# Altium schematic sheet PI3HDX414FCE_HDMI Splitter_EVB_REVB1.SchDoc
size 386 x 246 mm
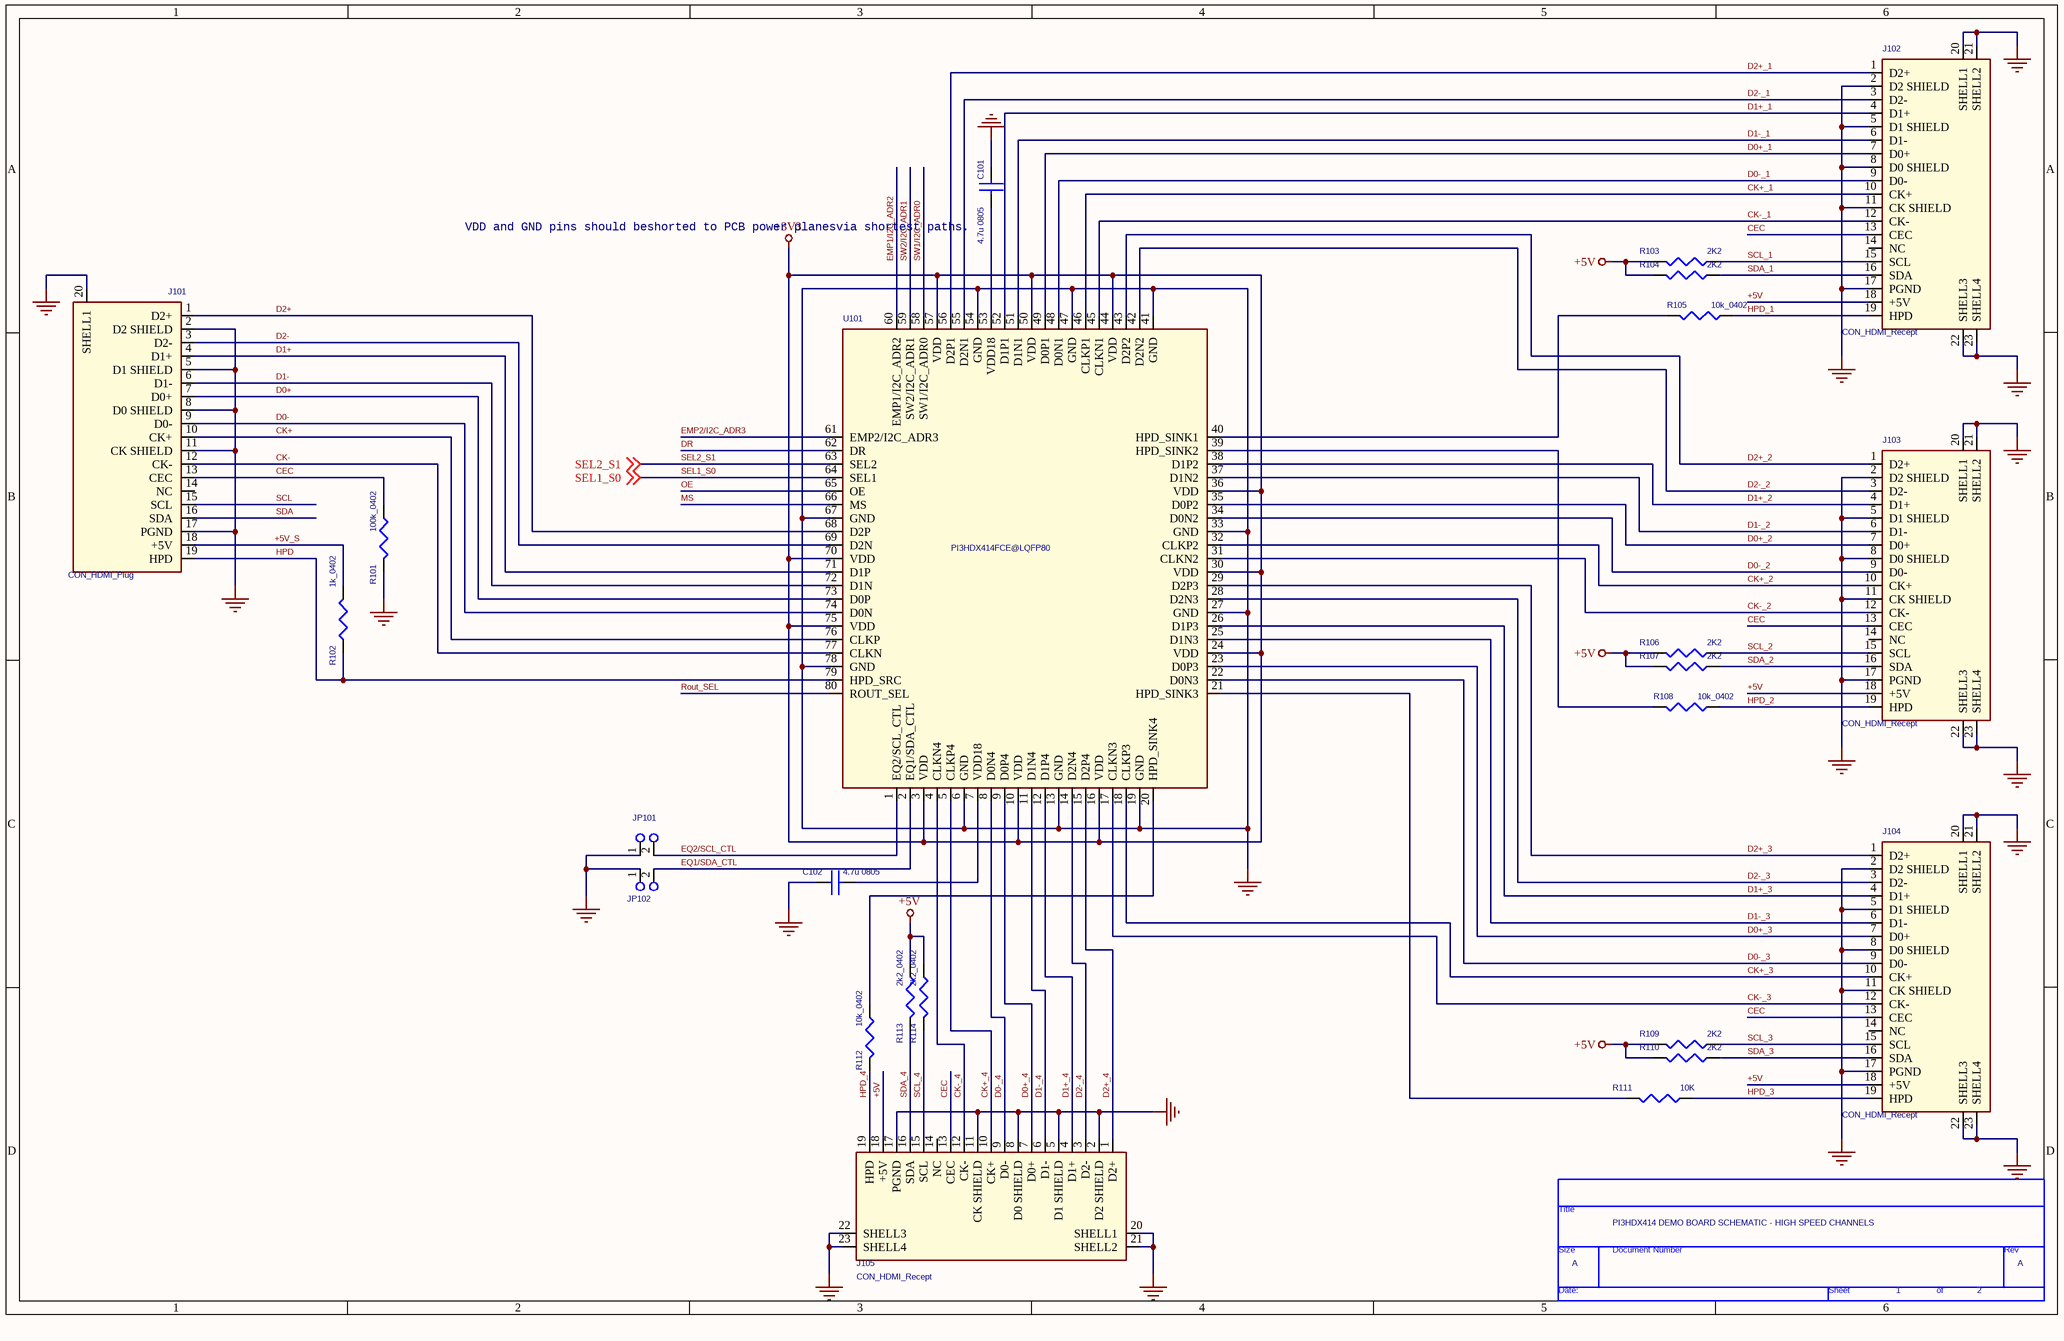
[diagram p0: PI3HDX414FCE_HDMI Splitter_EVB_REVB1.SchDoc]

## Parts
*  Page Count: 2  Page Number: 1  Page Size: A  Title: PI3HDX414 DEMO BOARD SCHEMATIC - HIGH SPEED CHANNELS  (hidden comment: TitleBlock0)  (graphical)
C101  4.7u 0805  [CAP@CC_0805]
C102  4.7u 0805  [CAP@CC_0805]
J101  CON_HDMI_Plug  [CON_HDMI_Plug]
J102  CON_HDMI_Recept  [CON_HDMI_Recept]
J103  CON_HDMI_Recept  [CON_HDMI_Recept]
J104  CON_HDMI_Recept  [CON_HDMI_Recept]
J105  CON_HDMI_Recept  [CON_HDMI_Recept]
JP101  2x1 Pin Header  [2x1 Pin Header]  (value not drawn)
JP102  2x1 Pin Header  [2x1 Pin Header]  (value not drawn)
R101  100k_0402  [R_0402]
R102  1k_0402  [R_0402]
R103  2K2  [RES@R_0402]
R104  2K2  [RES@R_0402]
R105  10k_0402  [R_0402]
R106  2K2  [RES@R_0402]
R107  2K2  [RES@R_0402]
R108  10k_0402  [R_0402]
R109  2K2  [RES@R_0402]
R110  2K2  [RES@R_0402]
R111  10K  [RES@R_0402]
R112  10k_0402  [R_0402]
R113  2k2_0402  [R_0402]
R114  2k2_0402  [R_0402]
U101  PI3HDX414FCE@LQFP80  [FC80]

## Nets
+3V3: U101.3(VDD) U101.10(VDD) U101.16(VDD) U101.24(VDD) U101.30(VDD) U101.36(VDD) U101.44(VDD) U101.50(VDD) U101.57(VDD) U101.70(VDD) U101.75(VDD)
+5V: J102.18(+5V) J103.18(+5V) J104.18(+5V) J105.18(+5V) R103.2 R104.2 R106.2 R107.2 R109.2 R110.2 R113.1 R114.1
GND: C101.1 C102.1 J101.2(D2_SHIELD) J101.5(D1_SHIELD) J101.8(D0_SHIELD) J101.11(CK_SHIELD) J101.17(PGND) J101.20(SHELL1) J102.2(D2_SHIELD) J102.5(D1_SHIELD) J102.8(D0_SHIELD) J102.11(CK_SHIELD) J102.17(PGND) J102.20(SHELL1) J102.21(SHELL2) J102.22(SHELL3) J102.23(SHELL4) J103.2(D2_SHIELD) J103.5(D1_SHIELD) J103.8(D0_SHIELD) J103.11(CK_SHIELD) J103.17(PGND) J103.20(SHELL1) J103.21(SHELL2) J103.22(SHELL3) J103.23(SHELL4) J104.2(D2_SHIELD) J104.5(D1_SHIELD) J104.8(D0_SHIELD) J104.11(CK_SHIELD) J104.17(PGND) J104.20(SHELL1) J104.21(SHELL2) J104.22(SHELL3) J104.23(SHELL4) J105.2(D2_SHIELD) J105.5(D1_SHIELD) J105.8(D0_SHIELD) J105.11(CK_SHIELD) J105.17(PGND) J105.20(SHELL1) J105.21(SHELL2) J105.22(SHELL3) J105.23(SHELL4) JP101.1 JP102.1 R101.2 U101.6(GND) U101.13(GND) U101.19(GND) U101.27(GND) U101.33(GND) U101.41(GND) U101.47(GND) U101.54(GND) U101.67(GND) U101.78(GND)
+5V_S: J101.18(+5V) R102.2
CEC: J101.13(CEC) J102.13(CEC) J103.13(CEC) J104.13(CEC) J105.13(CEC) R101.1
CK+: J101.10(CK+) U101.76(CLKP)
CK+_1: J102.10(CK+) U101.46(CLKP1)
CK+_2: J103.10(CK+) U101.32(CLKP2)
CK+_3: J104.10(CK+) U101.18(CLKP3)
CK+_4: J105.10(CK+) U101.5(CLKP4)
CK-: J101.12(CK-) U101.77(CLKN)
CK-_1: J102.12(CK-) U101.45(CLKN1)
CK-_2: J103.12(CK-) U101.31(CLKN2)
CK-_3: J104.12(CK-) U101.17(CLKN3)
CK-_4: J105.12(CK-) U101.4(CLKN4)
D0+: J101.7(D0+) U101.73(D0P)
D0+_1: J102.7(D0+) U101.49(D0P1)
D0+_2: J103.7(D0+) U101.35(D0P2)
D0+_3: J104.7(D0+) U101.23(D0P3)
D0+_4: J105.7(D0+) U101.9(D0P4)
D0-: J101.9(D0-) U101.74(D0N)
D0-_1: J102.9(D0-) U101.48(D0N1)
D0-_2: J103.9(D0-) U101.34(D0N2)
D0-_3: J104.9(D0-) U101.22(D0N3)
D0-_4: J105.9(D0-) U101.8(D0N4)
D1+: J101.4(D1+) U101.71(D1P)
D1+_1: J102.4(D1+) U101.52(D1P1)
D1+_2: J103.4(D1+) U101.38(D1P2)
D1+_3: J104.4(D1+) U101.26(D1P3)
D1+_4: J105.4(D1+) U101.12(D1P4)
D1-: J101.6(D1-) U101.72(D1N)
D1-_1: J102.6(D1-) U101.51(D1N1)
D1-_2: J103.6(D1-) U101.37(D1N2)
D1-_3: J104.6(D1-) U101.25(D1N3)
D1-_4: J105.6(D1-) U101.11(D1N4)
D2+: J101.1(D2+) U101.68(D2P)
D2+_1: J102.1(D2+) U101.56(D2P1)
D2+_2: J103.1(D2+) U101.43(D2P2)
D2+_3: J104.1(D2+) U101.29(D2P3)
D2+_4: J105.1(D2+) U101.15(D2P4)
D2-: J101.3(D2-) U101.69(D2N)
D2-_1: J102.3(D2-) U101.55(D2N1)
D2-_2: J103.3(D2-) U101.42(D2N2)
D2-_3: J104.3(D2-) U101.28(D2N3)
D2-_4: J105.3(D2-) U101.14(D2N4)
DR: U101.62(DR)
EMP1/I2C_ADR2: U101.60(EMP1/I2C_ADR2)
EMP2/I2C_ADR3: U101.61(EMP2/I2C_ADR3)
EQ1/SDA_CTL: JP102.2 U101.2(EQ1/SDA_CTL)
EQ2/SCL_CTL: JP101.2 U101.1(EQ2/SCL_CTL)
HPD: J101.19(HPD) R102.1 U101.79(HPD_SRC)
HPD_1: J102.19(HPD) R105.1
HPD_2: J103.19(HPD) R108.1
HPD_3: J104.19(HPD) R111.1
HPD_4: J105.19(HPD) R112.2
MS: U101.66(MS)
OE: U101.65(OE)
Rout_SEL: U101.80(ROUT_SEL)
SCL: J101.15(SCL)
SCL_1: J102.15(SCL) R103.1
SCL_2: J103.15(SCL) R106.1
SCL_3: J104.15(SCL) R109.1
SCL_4: J105.15(SCL) R114.2
SDA: J101.16(SDA)
SDA_1: J102.16(SDA) R104.1
SDA_2: J103.16(SDA) R107.1
SDA_3: J104.16(SDA) R110.1
SDA_4: J105.16(SDA) R113.2
SEL1_S0: U101.64(SEL1) ; off-sheet SEL1_S0
SEL2_S1: U101.63(SEL2) ; off-sheet SEL2_S1
SW1/I2C_ADR0: U101.58(SW1/I2C_ADR0)
SW2/I2C_ADR1: U101.59(SW2/I2C_ADR1)
NetC101_2: C101.2 U101.53(VDD18)
NetC102_2: C102.2 U101.7(VDD18)
NetR105_2: R105.2 U101.40(HPD_SINK1)
NetR108_2: R108.2 U101.39(HPD_SINK2)
NetR111_2: R111.2 U101.21(HPD_SINK3)
NetR112_1: R112.1 U101.20(HPD_SINK4)

Not connected (* = marked no-connect by the designer): J101 14(NC); J102 14(NC); J103 14(NC); J104 14(NC); J105 14(NC)

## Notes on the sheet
- VDD and GND pins should beshorted to PCB power planesvia shortest paths.

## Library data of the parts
C101 C102 = CHIP CAP0805
JP101 JP102 = 2x1 Pin Header_Dup1
R101 R102 R105 R108 R112-R114 = R_0402_Dup1
R103 R104 R106 R107 R109-R111 = CHIP RES0402_0
U101 = PI3HDX414FCE@LQFP80_3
